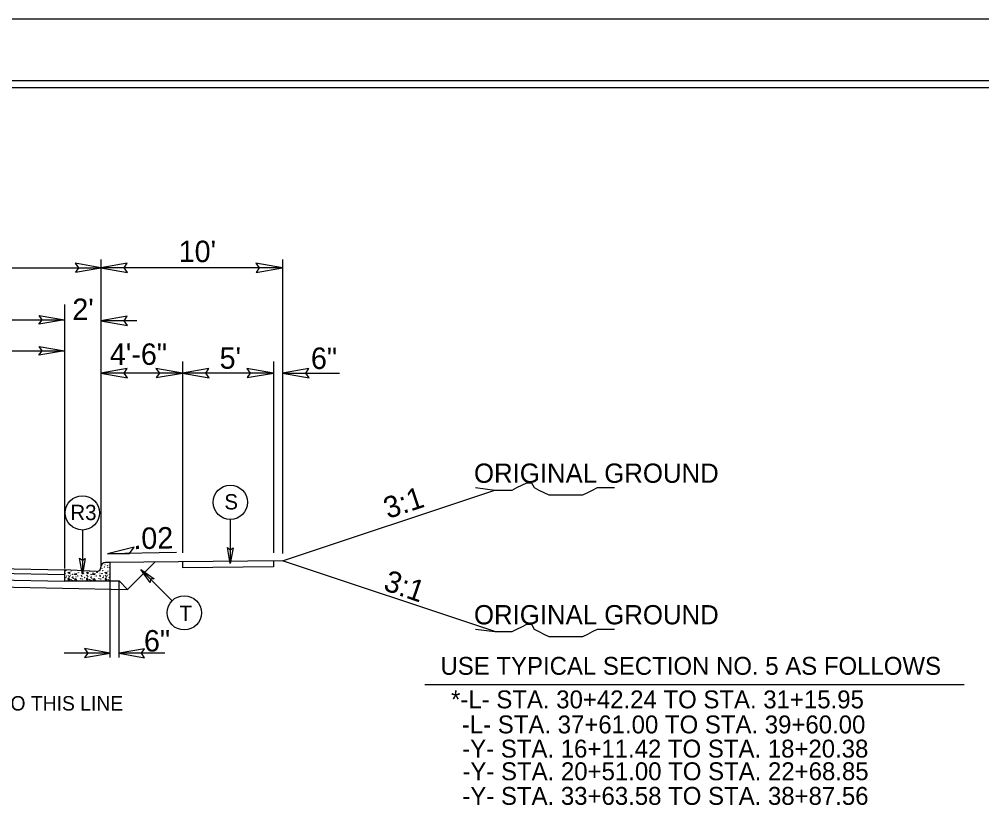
# Model space of a CAD drawing. Extents: x 958711 to 962106, y 831169 to 840840.
# Drawn here: x 959750.2 to 960099.9, y 838104 to 838391.1 of the extents above; entities that cross this region are included whole.
import ezdxf

# ---------------------------------------------------------------- set-up
doc = ezdxf.new("R2010")
doc.units = 0
for name, color, linetype in [('Old_Level_1', 7, 'Continuous'), ('Old_Level_11', 7, 'Continuous'), ('Old_Level_21', 7, 'Continuous'), ('Old_Level_3', 7, 'Continuous'), ('Prop Dimension Text', 7, 'Continuous'), ('Sheet Plot Border Inside CELL', 7, 'Continuous'), ('Sheet Plot Border Outside CELL', 7, 'Continuous'), ('Sheet Typical CELL', 7, 'Continuous'), ('Typical ID Circle CELL', 7, 'Continuous'), ('Typical Terminator CELL', 7, 'Continuous'), ('Typical Text ID Circle CELL', 7, 'Continuous')]:
    doc.layers.add(name, color=color, linetype=linetype)

msp = doc.modelspace()

# ---------------------------------------------------------------- linework, layer by layer
at = {"layer": 'Old_Level_1'}
for p, q in [((959779.86, 838303.69), (959779.86, 838192.12)), ((959845.9, 838303.69), (959845.9, 838196.87)), ((959213.41, 838300.69), (959779.86, 838300.69)), ((959845.9, 838300.69), (959779.86, 838300.69)), ((959766.65, 838287.38), (959766.65, 838191.41)), ((959766.65, 838287.38), (959766.65, 838191.91)), ((959563.12, 838281.8), (959766.65, 838281.8)), ((959792.92, 838281.46), (959779.86, 838281.46)), ((959656.6, 838270.55), (959766.65, 838270.55)), ((959809.57, 838266.61), (959809.57, 838197.04)), ((959842.59, 838266.61), (959842.59, 838197.04)), ((959809.57, 838262.44), (959779.86, 838262.44)), ((959842.59, 838262.44), (959809.57, 838262.44)), ((959845.9, 838262.44), (959866.56, 838262.44)), ((959845.9, 838194.18), (959923.08, 838219.91)), ((959494.95, 838196.39), (959766.65, 838190.9)), ((959807.39, 838197.2), (959782.28, 838196.7)), ((959845.9, 838194.18), (959782.93, 838193.55)), ((959842.59, 838194.15), (959842.59, 838191.97)), ((959923.08, 838168.45), (959845.9, 838194.18)), ((959653.23, 838191.47), (959766.65, 838189.17)), ((959789.59, 838183.79), (959799.52, 838193.72)), ((959809.57, 838193.82), (959809.57, 838191.64)), ((959842.59, 838191.97), (959809.57, 838191.64)), ((959653.23, 838189.04), (959766.65, 838186.75)), ((959653.23, 838186.54), (959789.59, 838183.79)), ((959783.22, 838186.92), (959786.52, 838186.85)), ((959783.22, 838159.02), (959783.22, 838186.92)), ((959786.52, 838186.85), (959789.59, 838183.79)), ((959786.52, 838159.02), (959786.52, 838186.85)), ((959783.22, 838160.61), (959766.62, 838160.61)), ((959803.12, 838160.61), (959786.52, 838160.61)), ((959897.55, 838149.22), (960093.49, 838149.22))]:
    msp.add_line(p, q, dxfattribs=at)
at = {"layer": 'Old_Level_11'}
for p, q in [((959792.02, 838199.11), (959782.28, 838196.7)), ((959790.29, 838196.86), (959792.02, 838199.11)), ((959782.28, 838196.7), (959790.29, 838196.86))]:
    msp.add_line(p, q, dxfattribs=at)
for points in [[(959836.29, 838299.03), (959845.9, 838300.69), (959836.24, 838302.39), (959837.46, 838300.69)], [(959789.46, 838302.34), (959779.86, 838300.69), (959789.53, 838298.97), (959788.3, 838300.69)], [(959789.46, 838283.12), (959779.86, 838281.46), (959789.53, 838279.75), (959788.3, 838281.46)], [(959789.46, 838264.1), (959779.86, 838262.44), (959789.53, 838260.73), (959788.3, 838262.44)], [(959799.97, 838260.79), (959809.57, 838262.44), (959799.91, 838264.15), (959801.14, 838262.44)], [(959819.18, 838264.1), (959809.57, 838262.44), (959819.24, 838260.73), (959818.01, 838262.44)], [(959832.99, 838260.79), (959842.59, 838262.44), (959832.93, 838264.15), (959834.16, 838262.44)], [(959855.5, 838264.1), (959845.9, 838262.44), (959855.56, 838260.73), (959854.33, 838262.44)]]:
    msp.add_lwpolyline(points, close=True, dxfattribs=at)
at = {"layer": 'Old_Level_21'}
for points in [[(959915.99, 838220.79), (959923.08, 838219.91), (959924.86, 838219.91), (959927.52, 838219.91), (959929.3, 838219.91), (959931.06, 838220.79), (959932.84, 838221.69), (959934.61, 838222.57), (959936.39, 838222.57), (959937.29, 838220.79), (959939.05, 838219.91), (959940.82, 838219.02), (959942.59, 838218.14), (959944.37, 838218.14), (959946.14, 838218.14), (959947.92, 838218.14), (959949.69, 838218.14), (959951.46, 838218.14), (959953.23, 838218.14), (959955.01, 838218.14), (959956.78, 838219.02), (959958.55, 838219.91), (959960.32, 838220.79), (959962.99, 838220.79), (959964.76, 838220.79), (959966.54, 838220.79)], [(959915.99, 838169.33), (959923.08, 838168.45), (959924.86, 838168.45), (959927.52, 838168.45), (959929.3, 838168.45), (959931.06, 838169.33), (959932.84, 838170.23), (959934.61, 838171.11), (959936.39, 838171.11), (959937.29, 838169.33), (959939.05, 838168.45), (959940.82, 838167.55), (959942.59, 838166.68), (959944.37, 838166.68), (959946.14, 838166.68), (959947.92, 838166.68), (959949.69, 838166.68), (959951.46, 838166.68), (959953.23, 838166.68), (959955.01, 838166.68), (959956.78, 838167.55), (959958.55, 838168.45), (959960.32, 838169.33), (959962.99, 838169.33), (959964.76, 838169.33), (959966.54, 838169.33)]]:
    msp.add_lwpolyline(points, dxfattribs=at)
at = {"layer": 'Old_Level_3'}
for p, q in [((959778.19, 838190.33), (959766.65, 838190.9)), ((959766.65, 838190.9), (959766.65, 838186.92)), ((959779.89, 838191.36), (959779.74, 838191.39)), ((959779.77, 838191.51), (959779.89, 838191.36)), ((959782.93, 838193.55), (959781.56, 838193.55)), ((959783.22, 838190.23), (959783.22, 838193.27)), ((959767.91, 838189.97), (959768.49, 838190)), ((959768.49, 838189.42), (959767.91, 838189.97)), ((959768.12, 838187.95), (959767.94, 838187.33)), ((959767.94, 838187.33), (959768.58, 838187.3)), ((959768.58, 838187.3), (959768.12, 838187.95)), ((959768.49, 838190), (959768.49, 838189.42)), ((959770.17, 838189.36), (959771, 838189.6)), ((959770.91, 838189.11), (959770.17, 838189.36)), ((959770.85, 838187.64), (959770.29, 838187.24)), ((959770.29, 838187.24), (959771.19, 838187.03)), ((959771.19, 838187.03), (959770.85, 838187.64)), ((959771, 838189.6), (959770.91, 838189.11)), ((959774.63, 838189.97), (959775.22, 838190)), ((959775.22, 838189.42), (959774.63, 838189.97)), ((959774.84, 838187.95), (959774.67, 838187.33)), ((959774.67, 838187.33), (959775.3, 838187.3)), ((959775.3, 838187.3), (959774.84, 838187.95)), ((959775.22, 838190), (959775.22, 838189.42)), ((959776.9, 838189.36), (959777.73, 838189.6)), ((959777.64, 838189.11), (959776.9, 838189.36)), ((959777.58, 838187.64), (959777.02, 838187.24)), ((959777.02, 838187.24), (959777.92, 838187.03)), ((959777.92, 838187.03), (959777.58, 838187.64)), ((959777.73, 838189.6), (959777.64, 838189.11)), ((959778.19, 838190.33), (959778.19, 838190.33)), ((959781.36, 838189.97), (959781.95, 838190)), ((959781.95, 838189.42), (959781.36, 838189.97)), ((959781.57, 838187.95), (959781.4, 838187.33)), ((959781.4, 838187.33), (959782.04, 838187.3)), ((959782.04, 838187.3), (959781.57, 838187.95)), ((959781.95, 838190), (959781.95, 838189.42)), ((959783.22, 838186.92), (959783.22, 838190.23)), ((959766.65, 838186.92), (959783.22, 838186.92))]:
    msp.add_line(p, q, dxfattribs=at)
for centre in [(959767.13, 838190.62), (959779.48, 838190.59), (959780.25, 838191.42), (959780.28, 838192.71), (959780.59, 838190.62), (959781.24, 838191.91), (959781.39, 838192.83), (959782.25, 838192.46), (959782.41, 838191.73), (959783.17, 838191.82), (959766.86, 838189.51), (959767.19, 838188.04), (959767.35, 838188.59), (959768.15, 838188.93), (959768.4, 838188.38), (959768.92, 838188.83), (959769.07, 838190.43), (959769.07, 838187.3), (959769.5, 838188.16), (959769.59, 838187.06), (959769.62, 838189.23), (959769.8, 838188.35), (959769.89, 838187.83), (959770.32, 838189.82), (959770.85, 838188.35), (959771.49, 838188.62), (959771.77, 838189.97), (959772.45, 838187.73), (959772.85, 838189.57), (959772.88, 838188.77), (959772.97, 838188.5), (959773.12, 838187.58), (959773.59, 838189.51), (959773.92, 838188.04), (959774.08, 838188.59), (959774.88, 838188.93), (959775.12, 838188.38), (959775.65, 838188.83), (959775.8, 838187.3), (959776.23, 838188.16), (959776.31, 838187.06), (959776.35, 838189.23), (959776.53, 838188.35), (959776.62, 838187.83), (959777.05, 838189.82), (959777.58, 838188.35), (959778.22, 838188.62), (959778.5, 838189.97), (959779.17, 838187.73), (959779.57, 838189.57), (959779.61, 838188.77), (959779.7, 838188.5), (959779.85, 838187.58), (959780.31, 838189.51), (959780.65, 838188.04), (959780.81, 838188.59), (959781.61, 838188.93), (959781.85, 838188.38), (959782.37, 838188.83), (959782.53, 838190.43), (959782.53, 838187.3), (959782.96, 838188.16), (959783.04, 838187.06), (959783.07, 838189.23)]:
    msp.add_circle(centre, 0.0432, dxfattribs=at)
for centre, radius, start, end in [((959772.75, 838190.59), 0.0432, 164.1199, 10.1626), ((959778.27, 838191.96), 1.64, 267.1376, 358.9266), ((959781.56, 838191.9), 1.66, 90, 178.9266), ((959782.93, 838193.27), 0.287, 0, 90), ((959783.04, 838193.48), 0.0432, 169.6531, 280.3469), ((959775.8, 838190.43), 0.0432, 162.062, 12.2205), ((959783.26, 838188.35), 0.0432, 150.4173, 209.5827)]:
    msp.add_arc(centre, radius, start, end, dxfattribs=at)
at = {"layer": 'Sheet Plot Border Inside CELL'}
msp.add_lwpolyline([(960390.3, 838368.62), (958723.8, 838368.62), (958723.8, 837313.52), (960390.3, 837313.52)], close=True, dxfattribs=at)
at = {"layer": 'Sheet Plot Border Outside CELL'}
msp.add_lwpolyline([(960394.8, 838391.07), (958710.8, 838391.07), (958710.8, 837291.07), (960394.8, 837291.07)], close=True, dxfattribs=at)
at = {"layer": 'Sheet Typical CELL'}
msp.add_lwpolyline([(960377.8, 838366.07), (958877.8, 838366.07), (958877.8, 837316.07), (960377.8, 837316.07)], close=True, dxfattribs=at)
at = {"layer": 'Typical ID Circle CELL'}
for p, q in [((959826.93, 838209.26), (959826.93, 838193.17)), ((959773.17, 838205.39), (959773.17, 838189.3)), ((959805.78, 838179.68), (959794.4, 838191.06))]:
    msp.add_line(p, q, dxfattribs=at)
for centre in [(959826.93, 838215.48), (959773.17, 838211.61), (959810.18, 838175.28)]:
    msp.add_circle(centre, 6.23, dxfattribs=at)
at = {"layer": 'Typical Terminator CELL'}
for points in [[(959770.63, 838299.1), (959779.86, 838300.69), (959770.58, 838302.33), (959771.76, 838300.69)], [(959757.43, 838283.39), (959766.65, 838281.8), (959757.38, 838280.16), (959758.55, 838281.8)], [(959757.43, 838272.14), (959766.65, 838270.55), (959757.38, 838268.91), (959758.55, 838270.55)], [(959827.92, 838198.94), (959826.93, 838193.17), (959825.9, 838198.97), (959826.93, 838198.23)], [(959774.16, 838195.06), (959773.17, 838189.3), (959772.15, 838195.09), (959773.17, 838194.36)], [(959797.78, 838186.28), (959794.4, 838191.06), (959799.23, 838187.68), (959797.98, 838187.48)], [(959774, 838159.02), (959783.22, 838160.61), (959773.95, 838162.25), (959775.13, 838160.61)], [(959795.75, 838162.19), (959786.52, 838160.61), (959795.8, 838158.97), (959794.62, 838160.61)]]:
    msp.add_lwpolyline(points, close=True, dxfattribs=at)

# ---------------------------------------------------------------- texts
at = {"layer": 'Old_Level_1'}
for s, height, p in [('USE TYPICAL SECTION NO. 5 AS FOLLOWS', 6.5088, (959903.28, 838152.74)), ('GRADE TO THIS LINE', 5.2473, (959715.87, 838139.76)), ('*-L- STA. 30+42.24 TO STA. 31+15.95', 6.5088, (959907.13, 838140.55)), ('-L- STA. 37+61.00 TO STA. 39+60.00', 6.5088, (959911.05, 838131.44)), ('-Y- STA. 16+11.42 TO STA. 18+20.38', 6.5088, (959911.18, 838122.65)), ('-Y- STA. 20+51.00 TO STA. 22+68.85', 6.5088, (959911.26, 838114.42)), ('-Y- STA. 33+63.58 TO STA. 38+87.56', 6.5088, (959911.24, 838105.47))]:
    msp.add_text(s, height=height, dxfattribs=at).set_placement(p)
at = {"layer": 'Old_Level_21'}
for p in [(959915.45, 838222.54), (959915.45, 838171.08)]:
    msp.add_text('ORIGINAL GROUND', height=7, dxfattribs=at).set_placement(p)
at = {"layer": 'Old_Level_3'}
for s, p in [("10'", (959808.16, 838302.76)), ("2'", (959769.52, 838281.71)), ('4\'-6"', (959783.16, 838265.41)), ("5'", (959823.03, 838264)), ('6"', (959856.21, 838263.92))]:
    msp.add_text(s, height=7.801, dxfattribs=at).set_placement(p)
for rotation, p in [(18.4348, (959884.2, 838209.36)), (341.0454, (959882.14, 838183.68))]:
    msp.add_text('3:1', height=7.801, rotation=rotation, dxfattribs=at).set_placement(p)
at = {"layer": 'Prop Dimension Text'}
for s, rotation, p in [('.02', 1.1839, (959791.77, 838198.39)), ('6"', 0, (959795.55, 838161.21))]:
    msp.add_text(s, height=7.801, rotation=rotation, dxfattribs=at).set_placement(p)
at = {"layer": 'Typical Text ID Circle CELL'}
for s, height, p in [('S', 5.57, (959824.76, 838212.85)), ('R3', 5.572, (959768.79, 838208.98)), ('T', 5.57, (959808.47, 838172.3))]:
    msp.add_text(s, height=height, dxfattribs=at).set_placement(p)

doc.saveas('drawing.dxf')
